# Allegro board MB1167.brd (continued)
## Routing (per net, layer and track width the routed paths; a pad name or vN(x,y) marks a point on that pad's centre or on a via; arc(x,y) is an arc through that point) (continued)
D11: length 133
  TOP w0.102: U9.G4 75.52,103.76 73.51,103.76 72.77,103.02 72.77,102.11 72.11,101.45 72.11,101.09 71.88,100.86 ; 65.9,82.8 65.9,81.42 66.04,81.28 66.04,79.73 U14.D2 ; v5(85.86,82.34) U13.P1
  TOP w0.127: v5(65.28,83.69) 65.34,83.69 65.9,83.14 65.9,82.8 ; CN10.20 v3(54.86,105.97) ; 71.88,100.86 v4(71.65,100.63) ; R55.2 v1(68.58,124.59)
  L4_SIG w0.102: v4(71.65,100.63) 71.6,100.58 69.37,100.58 63.98,105.97 v3(54.86,105.97) ; v5(85.86,82.34) 85.86,82.85 85.58,83.13 74.86,83.13 74.52,82.8 v1(73.66,82.8) 73.46,83.01 66.14,83.01 65.46,83.69 v5(65.28,83.69)
  BOTTOM w0.127: v4(71.65,100.63) 71.09,100.63 70.83,100.37 70.83,100.19 71.7,99.31 71.7,99.13 71.52,98.95 71.34,98.95 70.47,99.83 70.29,99.83 70.11,99.65 70.11,99.47 70.98,98.59 70.98,98.41 70.78,98.21 70.6,98.21 69.72,99.08 69.54,99.08 69.36,98.9 69.36,98.72 70.24,97.85 70.24,97.67 70.06,97.49 69.88,97.49 69.58,97.79 69.4,97.79 69.22,97.61 69.22,97.43 69.52,97.13 69.52,96.95 69.22,96.65 69.22,88.04 69.34,87.91 72.11,87.91 72.24,87.78 72.24,87.53 72.11,87.4 69.34,87.4 69.22,87.27 69.22,87.02 69.34,86.89 73.1,86.89 73.23,86.77 73.23,86.49 73.1,86.36 70.28,86.36 70.15,86.23 70.15,85.98 70.28,85.85 73.43,85.85 73.56,85.72 73.56,85.45 73.43,85.32 71.3,85.32 71.17,85.19 71.17,84.94 71.3,84.81 73.43,84.81 73.56,84.68 73.56,84.43 73.43,84.3 72.31,84.3 72.19,84.18 72.19,83.92 72.31,83.79 73.43,83.79 73.56,83.67 73.56,83.41 73.43,83.29 72.72,83.29 72.59,83.16 72.59,82.93 72.72,82.8 v1(73.66,82.8) ; v1(68.58,124.59) 69.22,123.95 69.22,117.35 57.84,105.97 v3(54.86,105.97)
D12: length 129.8
  TOP w0.102: v5(64.84,81.85) 65.28,81.41 65.28,79.74 U14.E2 ; U9.F5 76.51,102.77 75.67,102.77 75.53,102.63 75.53,101.11 75.19,100.76 73.33,100.76 v4(73.15,100.58) ; v5(86.66,81.54) U13.N2
  TOP w0.127: CN10.17 v3(53.42,107.24) ; R66.2 v1(67.56,121.28)
  L4_SIG w0.102: v3(53.42,107.24) 52.83,106.65 52.83,105.69 53.09,105.44 55.47,105.44 55.57,105.33 55.57,104.42 55.67,104.32 55.9,104.32 56,104.42 56,105.51 56.11,105.61 56.31,105.61 56.41,105.51 56.41,104.42 56.51,104.32 56.72,104.32 56.82,104.42 56.82,105.51 56.92,105.61 57.12,105.61 57.22,105.51 57.22,104.42 57.33,104.32 57.53,104.32 57.63,104.42 57.63,105.51 57.73,105.61 57.94,105.61 58.04,105.51 58.04,104.42 58.14,104.32 58.34,104.32 58.44,104.42 58.44,105.51 58.54,105.61 58.75,105.61 58.85,105.51 58.85,104.42 58.95,104.32 59.15,104.32 59.26,104.42 59.26,105.51 59.36,105.61 59.56,105.61 59.66,105.51 59.66,104.42 59.76,104.32 59.97,104.32 60.07,104.42 60.07,105.51 60.17,105.61 60.37,105.61 60.48,105.51 60.48,104.42 60.58,104.32 60.78,104.32 60.88,104.42 60.88,105.51 60.98,105.61 61.19,105.61 61.29,105.51 61.29,104.42 61.39,104.32 61.59,104.32 61.69,104.42 61.69,105.51 61.8,105.61 62,105.61 62.1,105.51 62.1,104.42 62.2,104.32 62.41,104.32 62.51,104.42 62.51,105.51 62.61,105.61 62.81,105.61 62.91,105.51 62.91,104.42 63.02,104.32 63.22,104.32 63.32,104.42 63.32,105.51 63.42,105.61 63.62,105.61 63.73,105.51 63.73,104.42 63.83,104.32 65.02,104.32 69.14,100.2 72.77,100.2 v4(73.15,100.58) ; v5(86.66,81.54) 86.4,81.54 86.03,81.92 84.84,81.92 84.51,82.25 75.74,82.25 75.59,82.09 v1(74.93,82.09) 74.81,81.98 72.95,81.98 72.85,82.08 72.85,82.3 72.75,82.4 72.55,82.4 72.44,82.3 72.44,82.08 72.34,81.98 64.96,81.98 v5(64.84,81.85)
  BOTTOM w0.127: v4(73.15,100.58) 73.15,98.86 70.36,96.06 70.36,91.16 70.48,91.03 74.8,91.03 74.93,90.91 v1(74.93,82.09) ; v1(67.56,121.28) 67.56,117.6 57.91,107.95 54.13,107.95 v3(53.42,107.24)
D13: length 142.8
  TOP w0.102: 74.15,97.79 75.29,98.93 75.29,100.44 75.91,101.06 U9.G6 ; U13.R1 84.27,81.94 ; 84.27,82.63 84.93,82.63 85.06,82.5 v5(85.06,82.34) ; v5(64.14,81.79) 64.52,81.41 64.52,80.8 64.52,80.79 64.52,79.75 U14.F2
  TOP w0.127: 74.15,97.79 73.41,97.05 73.41,97.03 v4(73.03,96.65) ; 84.27,81.94 84.15,81.94 84.02,82.07 84.02,82.5 84.15,82.63 84.27,82.63 ; CN10.35 53.03,95.81 v3(53.42,96.2) ; R59.2 v1(75.18,124.71)
  L4_SIG w0.102: v5(85.06,82.34) 85.37,82.34 85.5,82.47 85.5,82.7 85.37,82.83 84.76,82.83 84.63,82.7 84.63,82.68 84.51,82.55 84.21,82.55 84.11,82.65 84.11,82.73 84,82.83 83.8,82.83 83.7,82.73 83.7,82.65 83.6,82.55 83.39,82.55 83.29,82.65 83.29,82.73 83.19,82.83 82.99,82.83 82.89,82.73 82.89,82.65 82.79,82.55 82.58,82.55 82.48,82.65 82.48,82.73 82.38,82.83 82.18,82.83 82.07,82.73 82.07,82.65 81.97,82.55 81.77,82.55 81.67,82.65 81.67,82.73 81.57,82.83 81.36,82.83 81.26,82.73 81.26,82.65 81.16,82.55 80.96,82.55 80.85,82.65 80.85,82.73 80.75,82.83 80.55,82.83 80.45,82.73 80.45,82.65 80.35,82.55 80.14,82.55 80.04,82.65 80.04,82.73 79.94,82.83 79.74,82.83 79.64,82.73 79.64,82.65 79.53,82.55 79.33,82.55 79.23,82.65 79.23,82.73 79.13,82.83 78.92,82.83 78.82,82.73 78.82,82.65 78.72,82.55 78.52,82.55 78.42,82.65 78.42,82.73 78.31,82.83 78.11,82.83 78.01,82.73 78.01,82.65 77.91,82.55 77.09,82.55 v1(76.96,82.68) 74.9,82.68 74.56,82.33 73.42,82.33 73.05,82.7 72.24,82.7 71.87,82.33 64.55,82.33 64.14,81.92 v5(64.14,81.79) ; v4(73.03,96.65) 69.9,96.65 69.77,96.52 69.77,95.94 69.65,95.81 66.47,95.81 66.34,95.68 66.34,94.54 66.22,94.41 66.03,94.41 65.91,94.54 65.91,95.66 65.81,95.76 65.6,95.76 65.5,95.66 65.5,94.51 65.4,94.41 65.2,94.41 65.09,94.51 65.09,95.66 64.99,95.76 64.79,95.76 64.69,95.66 64.69,94.51 64.59,94.41 64.38,94.41 64.28,94.51 64.28,95.66 64.18,95.76 63.98,95.76 63.87,95.66 63.87,94.51 63.77,94.41 63.57,94.41 63.47,94.51 63.47,95.66 63.37,95.76 63.16,95.76 63.06,95.66 63.06,94.51 62.96,94.41 62.76,94.41 62.66,94.51 62.66,95.66 62.55,95.76 62.35,95.76 62.25,95.66 62.25,94.51 62.15,94.41 61.94,94.41 61.84,94.51 61.84,95.66 61.74,95.76 61.54,95.76 61.44,95.66 61.44,94.51 61.33,94.41 61.13,94.41 61.03,94.51 61.03,95.66 60.93,95.76 60.73,95.76 60.62,95.66 60.62,94.51 60.52,94.41 60.32,94.41 60.22,94.51 60.22,95.66 60.12,95.76 59.91,95.76 59.81,95.66 59.81,94.51 59.71,94.41 59.51,94.41 59.4,94.51 59.4,95.66 59.3,95.76 59.1,95.76 59,95.66 59,94.51 58.9,94.41 58.69,94.41 58.59,94.51 58.59,95.66 58.49,95.76 58.29,95.76 58.19,95.66 58.19,94.51 58.08,94.41 57.88,94.41 57.78,94.51 57.78,95.66 57.68,95.76 53.85,95.76 v3(53.42,96.2)
  BOTTOM w0.127: v3(53.42,96.2) 53.42,96.2 53.98,96.75 56.62,96.75 74.42,114.55 74.42,121.25 74.8,121.64 74.8,123.44 75.18,123.83 v1(75.18,124.71) ; v4(73.03,96.65) 73.03,96.11 76.96,92.18 v1(76.96,82.68)
D14: length 135.3
  TOP w0.102: U14.F1 v5(64.92,80.64) ; v5(86.66,80.74) U13.N3 ; U9.F6 76.29,100.75 76.29,98.39 75.69,97.79
  TOP w0.127: 75.69,97.79 v4(74.55,96.65) ; CN10.37 53.01,94.54 53.47,95 v3(53.47,95.21) ; v1(75.44,120.75) 75.31,120.75 73.79,122.28 R70.2
  L4_SIG w0.102: v4(74.55,96.65) 74.55,95.1 74.42,94.97 74.12,94.97 73.99,95.1 73.99,96.15 73.86,96.28 73.62,96.28 73.52,96.18 73.52,95 73.41,94.89 73.21,94.89 73.11,95 73.11,96.07 72.99,96.19 72.82,96.19 72.7,96.07 72.7,95 72.6,94.89 72.4,94.89 72.3,95 72.3,96.18 72.2,96.28 71.99,96.28 71.89,96.18 71.89,95 71.79,94.89 71.59,94.89 71.48,95 71.48,96.18 71.38,96.28 70.21,96.28 70.08,96.15 70.08,94.21 69.95,94.08 69.72,94.08 69.62,94.18 69.62,95.4 69.52,95.5 69.31,95.5 69.21,95.4 69.21,94.18 69.11,94.08 68.91,94.08 68.81,94.18 68.81,95.4 68.7,95.5 68.5,95.5 68.4,95.4 68.4,94.18 68.3,94.08 68.09,94.08 67.99,94.18 67.99,95.4 67.89,95.5 67.69,95.5 67.59,95.4 67.59,94.18 67.49,94.08 67.28,94.08 67.18,94.18 67.18,95.4 67.08,95.5 66.88,95.5 66.77,95.4 66.77,94.18 66.67,94.08 57.43,94.08 57.3,94.21 57.3,95.33 57.18,95.45 53.71,95.45 v3(53.47,95.21) ; v5(64.92,80.64) 64.92,80.89 65.39,81.37 71.64,81.37 71.78,81.23 77.27,81.23 v1(77.46,81.42) 77.46,81.06 77.6,80.92 81.03,80.92 81.15,81.05 81.15,81.46 81.28,81.58 81.43,81.58 81.56,81.46 81.56,81.05 81.69,80.92 81.86,80.92 81.99,81.05 81.99,81.46 82.12,81.58 84.18,81.58 84.61,81.15 86.97,81.15 87.1,81.03 87.1,80.87 86.97,80.74 v5(86.66,80.74)
  BOTTOM w0.127: v1(77.46,81.42) 77.85,81.81 77.85,92.43 74.42,95.86 74.42,96.52 v4(74.55,96.65) ; v3(53.47,95.21) 53.89,95.63 56.64,95.63 75.18,114.17 75.18,120.5 v1(75.44,120.75)
D15: length 134.1
  TOP w0.102: U14.G1 v5(64.16,80.64) ; 74.93,97.79 75.53,98.39 75.53,99.99 U9.G7 ; v5(85.06,81.54) U13.R2
  TOP w0.127: 74.93,97.79 v4(73.84,96.7) ; R71.2 75.18,121.67 v1(75.44,121.41) ; v3(54.86,96.24) 54.86,96.19 55.24,95.81 CN10.36
  L4_SIG w0.102: v5(85.06,81.54) 84.73,81.54 84.36,81.91 80.98,81.91 80.85,81.78 80.85,81.38 80.72,81.25 80.59,81.25 80.47,81.38 80.47,81.71 80.34,81.84 80.16,81.84 80.04,81.71 80.04,81.38 79.91,81.25 79.72,81.25 79.62,81.36 79.62,81.82 79.5,81.94 79.34,81.94 79.22,81.82 79.22,81.36 79.12,81.25 78.91,81.25 78.81,81.36 78.81,81.82 78.69,81.94 78.52,81.94 78.4,81.82 78.4,81.36 78.3,81.25 78.1,81.25 78,81.36 78,81.81 77.9,81.91 77.06,81.91 v1(76.96,81.81) 76.81,81.66 65.15,81.66 64.16,80.67 v5(64.16,80.64) ; v4(73.84,96.7) 73.84,96.94 73.71,97.07 69.6,97.07 69.47,96.94 69.47,96.32 69.34,96.19 69.19,96.19 69.06,96.32 69.06,96.88 68.94,97 68.76,97 68.63,96.88 68.63,96.32 68.5,96.19 68.33,96.19 68.22,96.29 68.22,96.98 68.12,97.08 67.92,97.08 67.82,96.98 67.82,96.29 67.72,96.19 67.51,96.19 67.41,96.29 67.41,96.98 67.31,97.08 67.11,97.08 67.01,96.98 67.01,96.29 66.9,96.19 66.7,96.19 66.6,96.29 66.6,96.98 66.5,97.08 66.29,97.08 66.19,96.98 66.19,96.29 66.09,96.19 65.89,96.19 65.79,96.29 65.79,96.98 65.68,97.08 65.48,97.08 65.38,96.98 65.38,96.29 65.28,96.19 65.08,96.19 64.97,96.29 64.97,96.98 64.87,97.08 64.67,97.08 64.57,96.98 64.57,96.29 64.47,96.19 64.26,96.19 64.16,96.29 64.16,96.98 64.06,97.08 63.86,97.08 63.75,96.98 63.75,96.18 63.64,96.06 63.47,96.06 63.35,96.18 63.35,96.98 63.25,97.08 63.04,97.08 62.94,96.98 62.94,96.18 62.82,96.06 62.65,96.06 62.54,96.18 62.54,96.98 62.43,97.08 62.23,97.08 62.13,96.98 62.13,96.18 62.01,96.06 61.84,96.06 61.72,96.18 61.72,96.98 61.62,97.08 61.42,97.08 61.32,96.98 61.32,96.18 61.2,96.06 61.03,96.06 60.91,96.18 60.91,96.98 60.81,97.08 60.6,97.08 60.5,96.98 60.5,96.21 60.38,96.09 60.22,96.09 60.1,96.21 60.1,96.98 60,97.08 59.79,97.08 59.69,96.98 59.69,96.23 59.57,96.11 59.4,96.11 59.28,96.23 59.28,96.98 59.18,97.08 58.98,97.08 58.88,96.98 58.88,96.18 58.76,96.06 58.59,96.06 58.47,96.18 58.47,96.98 58.37,97.08 58.17,97.08 58.06,96.98 58.06,96.21 57.95,96.09 57.78,96.09 57.66,96.21 57.66,96.98 57.56,97.08 57.35,97.08 57.25,96.98 57.25,96.18 57.13,96.06 56.96,96.06 56.85,96.18 56.85,96.98 56.74,97.08 56.54,97.08 56.44,96.98 56.44,96.18 56.32,96.06 56.15,96.06 56.03,96.18 56.03,96.83 55.91,96.95 55.75,96.95 55.63,96.83 55.63,96.29 55.52,96.19 54.91,96.19 v3(54.86,96.24)
  BOTTOM w0.127: v3(54.86,96.24) 55.09,96.01 56.48,96.01 74.8,114.33 74.8,120.9 75.31,121.41 v1(75.44,121.41) ; v4(73.84,96.7) 73.79,96.65 73.79,95.9 77.47,92.22 77.47,82.19 77.09,81.81 v1(76.96,81.81)
D16: length 117.6
  TOP w0.102: U13.E8 93.85,75.95 93.85,74.66
  TOP w0.127: 93.85,74.66 93.85,74.3 v5(95.25,72.9) ; v1(70.87,124.71) 70.99,124.84 R56.1 ; CN10.22 v3(54.86,104.7)
  L4_SIG w0.102: v3(54.86,104.7) 54.46,104.7 54.03,105.13 52.63,105.13 51.66,104.17 51.66,91.37 51.77,91.27 52.08,91.27 52.2,91.15 52.2,90.98 52.08,90.86 51.77,90.86 51.66,90.76 51.66,90.55 51.77,90.45 52.92,90.45 53.04,90.33 53.04,90.17 52.92,90.05 51.77,90.05 51.66,89.94 51.66,89.74 51.77,89.64 53.73,89.64 53.85,89.52 53.85,89.35 53.73,89.23 51.77,89.23 51.66,89.13 51.66,84.45 66.62,69.49 88.9,69.49 92.3,72.9 v5(95.25,72.9)
  BOTTOM w0.127: v3(54.86,104.7) 57.93,104.7 69.98,116.74 69.98,123.83 v1(70.87,124.71)
D17: length 120.5
  TOP w0.102: v5(94.66,76.74) U13.D7
  TOP w0.127: CN10.26 v3(54.86,102.16) ; R57.1 v1(72.39,124.71)
  L4_SIG w0.102: v3(54.86,102.16) 54.18,102.16 53.59,102.74 52.96,102.74 52.27,102.06 52.27,92.08 54.46,89.89 54.46,86.97 54.36,86.87 52.43,86.87 52.32,86.77 52.32,86.56 52.43,86.46 54.16,86.46 54.28,86.34 54.28,86.17 54.16,86.06 52.43,86.06 52.32,85.95 52.32,85.75 52.43,85.65 54.08,85.65 54.2,85.53 54.2,85.36 54.08,85.24 52.43,85.24 52.32,85.14 52.32,84.76 66.95,70.13 88.6,70.13 92.51,74.04 95.76,74.04 96.27,74.55 96.27,75.31 95.89,75.69 95.89,76.23 95.78,76.33 95.07,76.33 v5(94.66,76.74)
  BOTTOM w0.127: v3(54.86,102.16) 57.71,102.16 71.5,115.95 71.5,120.27 71.88,120.65 71.88,123.95 72.39,124.46 v1(72.39,124.71)
D18: length 116.6
  TOP w0.102: 94.7,74.66 94.7,75.9 U13.D8
  TOP w0.127: R68.1 v1(70.99,121.28) ; v5(95.22,73.53) 95.22,73.81 94.7,74.33 94.7,74.66 ; CN10.24 v3(54.86,103.43)
  L4_SIG w0.102: v5(95.22,73.53) 92.46,73.53 88.72,69.8 66.83,69.8 51.97,84.66 51.97,87.19 52.07,87.29 54.05,87.29 54.15,87.39 54.15,87.59 54.05,87.7 52.07,87.7 51.97,87.8 51.97,88 52.07,88.1 54.05,88.1 54.15,88.2 54.15,88.41 54.05,88.51 52.07,88.51 51.97,88.61 51.97,88.81 52.07,88.91 54.05,88.91 54.15,89.02 54.15,89.69 51.97,91.87 51.97,103.15 52.83,104.01 53.59,104.01 54.18,103.43 v3(54.86,103.43)
  BOTTOM w0.127: v1(70.99,121.28) 70.74,121.03 70.74,116.36 57.81,103.43 v3(54.86,103.43)
D19: length 115.2
  TOP w0.102: v5(95.86,74.68) U13.B9
  TOP w0.127: v1(72,119.9) 72,120 72.39,120.4 R69.1 ; CN10.27 v3(53.42,100.89)
  L4_SIG w0.102: v3(53.42,100.89) 52.58,100.05 52.58,92.3 54.79,90.09 54.79,89.81 54.89,89.7 55.19,89.7 55.32,89.58 55.32,89.43 55.19,89.3 54.89,89.3 54.79,89.2 54.79,88.99 54.89,88.89 55.8,88.89 55.91,88.79 55.91,88.59 55.8,88.49 54.89,88.49 54.79,88.38 54.79,88.18 54.89,88.08 55.8,88.08 55.91,87.98 55.91,87.77 55.8,87.67 54.89,87.67 54.79,87.57 54.79,87.37 54.89,87.27 55.8,87.27 55.91,87.16 55.91,86.96 55.8,86.86 54.89,86.86 54.79,86.76 54.79,86.56 54.89,86.45 55.8,86.45 55.91,86.35 55.91,86.15 55.8,86.05 54.89,86.05 54.79,85.95 54.79,84.91 54.69,84.81 53.13,84.81 53.01,84.69 53.01,84.52 53.13,84.4 54.69,84.4 54.79,84.3 54.79,84.1 54.69,84 54,84 53.9,83.89 53.9,83.69 54,83.59 54.69,83.59 54.79,83.49 54.79,82.73 67.08,70.43 88.47,70.43 92.46,74.42 95.61,74.42 v5(95.86,74.68)
  BOTTOM w0.127: v1(72,119.9) 72,115.86 57.73,101.6 54.13,101.6 v3(53.42,100.89)
D20: length 118.4
  TOP w0.102: v5(95.46,75.94) U13.C8
  TOP w0.127: R58.1 v1(73.79,124.71) ; CN10.32 v3(54.86,98.35)
  L4_SIG w0.102: v3(54.86,98.35) 54.15,99.06 53.42,99.06 52.88,98.53 52.88,92.46 56.21,89.13 56.21,85.8 56.11,85.7 55.19,85.7 55.09,85.6 55.09,85.39 55.19,85.29 56.11,85.29 56.21,85.19 56.21,84.99 56.11,84.89 55.19,84.89 55.09,84.78 55.09,84.58 55.19,84.48 56.11,84.48 56.21,84.38 56.21,84.17 56.11,84.07 55.19,84.07 55.09,83.97 55.09,83.77 55.19,83.67 56.11,83.67 56.21,83.56 56.21,83.36 56.11,83.26 55.19,83.26 55.09,83.16 55.09,82.96 55.19,82.85 56.11,82.85 56.21,82.75 56.21,81.81 67.21,70.82 88.37,70.82 92.25,74.7 92.25,76.05 92.38,76.17 92.66,76.17 92.79,76.05 92.79,75.39 92.91,75.26 93.17,75.26 93.29,75.39 93.29,76.05 93.42,76.17 93.63,76.17 93.76,76.05 93.76,75.34 93.86,75.23 94.06,75.23 94.16,75.34 94.16,76.08 94.28,76.2 94.45,76.2 94.57,76.08 94.57,75.34 94.67,75.23 94.88,75.23 94.98,75.34 94.98,75.84 95.08,75.94 v5(95.46,75.94)
  BOTTOM w0.127: v1(73.79,124.71) 73.79,124.15 73.27,123.63 73.27,115.44 56.18,98.35 v3(54.86,98.35)
D21: length 115.3
  TOP w0.102: v5(97.06,75.14) U13.A9
  TOP w0.127: v3(101.85,92.46) 101.04,93.27 CN11.39
  L4_SIG w0.102: v5(97.06,75.14) 96.65,75.55 96.65,76.94 97.66,77.95 97.66,87.68 101.85,91.87 v3(101.85,92.46)
  BOTTOM w0.127: v3(101.85,92.46) 87.6,92.46 87.35,92.71 87.35,104.02 87.22,104.14 86,104.14 85.83,104.32 85.83,104.61 85.95,104.74 87.22,104.74 87.35,104.87 87.35,105.12 87.22,105.25 85.95,105.25 85.83,105.38 85.83,107.49 85.7,107.62 85.19,107.62 85.06,107.75 85.06,108 85.19,108.13 85.7,108.13 85.83,108.25 85.83,108.64 85.34,109.12 84.83,109.12 84.67,108.96 84.49,108.96 84.31,109.14 84.31,109.32 84.58,109.6 84.58,109.78 84.41,109.96 84.23,109.96 83.95,109.68 83.77,109.68 83.59,109.86 83.59,110.04 83.75,110.2 83.75,110.38 83.52,110.62 83.2,110.62 83.08,110.74 83.08,111.15 82.95,111.28 82.69,111.28 82.57,111.15 82.57,110.31 82.44,110.19 82.06,110.19 81.93,110.31 81.93,111.25 81.81,111.38 81.55,111.38 81.43,111.25 81.43,110.74 81.3,110.62 81.05,110.62 80.92,110.74 80.92,111.25 80.79,111.38 79.86,111.38 79.73,111.25 79.73,110.74 79.6,110.62 79.35,110.62 79.22,110.74 79.22,111.25 79.1,111.38 78.74,111.38 78.61,111.25 78.61,110.82 78.49,110.69 78.18,110.69 78.05,110.82 78.05,115.64 78.18,115.76 79.98,115.76 80.11,115.89 80.11,116.14 79.98,116.27 78.18,116.27 78.05,116.4 78.05,116.65 78.18,116.78 79.98,116.78 80.11,116.91 80.11,117.16 79.98,117.29 78.18,117.29 78.05,117.41 78.05,117.67 78.18,117.8 79.98,117.8 80.11,117.92 80.11,118.18 79.98,118.3 78.18,118.3 78.05,118.43 78.05,118.68 78.18,118.81 79.98,118.81 80.11,118.94 80.11,119.19 79.98,119.32 78.18,119.32 78.05,119.45 78.05,119.7 78.18,119.83 79.98,119.83 80.11,119.95 80.11,120.21 79.98,120.34 78.18,120.34 78.05,120.46 78.05,120.72 78.18,120.84 79.98,120.84 80.11,120.97 80.11,121.14 79.98,121.27 79.5,121.27 79.38,121.39 79.38,121.65 79.5,121.78 79.98,121.78 80.11,121.9 80.11,122.16 79.98,122.28 79.63,122.28 79.5,122.41 79.5,122.66 79.63,122.79 79.98,122.79 80.11,122.92 80.11,123.21 79.98,123.34 79.63,123.34 79.5,123.46 79.5,123.72 79.63,123.84 80.62,123.84 80.75,123.97 80.75,124.31 80.62,124.43 79.63,124.43 79.5,124.56 79.5,125.09 79.63,125.22 R271.1
D22: length 113
  TOP w0.102: v5(95.46,76.74) U13.C7
  TOP w0.127: CN11.38 103.96,94.54 v3(103.5,95)
  L4_SIG w0.102: v5(95.46,76.74) 96.7,77.98 96.7,78.65 96.8,78.75 97.1,78.75 97.21,78.85 97.21,79.06 97.1,79.16 96.8,79.16 96.7,79.26 96.7,79.46 96.8,79.57 97.1,79.57 97.21,79.67 97.21,79.87 97.1,79.97 96.8,79.97 96.7,80.07 96.7,90.48 101.73,95.5 103,95.5 v3(103.5,95)
  BOTTOM w0.127: v3(103.5,95) 103.89,94.61 103.89,93.47 103.25,92.84 102.23,92.84 101.98,93.09 87.88,93.09 87.76,93.22 87.76,93.45 87.88,93.57 89.36,93.57 89.48,93.7 89.48,94.04 89.36,94.17 87.88,94.17 87.76,94.29 87.76,94.55 87.88,94.67 89.36,94.67 89.48,94.8 89.48,95.05 89.36,95.18 87.88,95.18 87.76,95.31 87.76,95.56 87.88,95.69 89.36,95.69 89.48,95.82 89.48,96.07 89.36,96.2 87.88,96.2 87.76,96.32 87.76,96.58 87.88,96.71 89.36,96.71 89.48,96.83 89.48,101.52 89.36,101.65 87.91,101.65 87.78,101.78 87.78,105.28 87.39,105.67 86.39,105.67 86.26,105.8 86.26,108.81 83.29,111.79 78.56,111.79 78.44,111.91 78.44,112.17 78.56,112.29 82.3,112.29 82.42,112.42 82.42,112.65 82.3,112.78 78.56,112.78 78.44,112.9 78.44,113.2 78.56,113.33 80.75,113.33 80.87,113.45 80.87,113.71 80.75,113.84 78.56,113.84 78.44,113.96 78.44,114.22 78.56,114.34 80.72,114.34 80.85,114.47 80.85,114.72 80.72,114.85 78.56,114.85 78.44,114.98 78.44,115.23 78.56,115.36 80.52,115.36 80.64,115.49 R279.1
D23: length 113.3
  TOP w0.102: v5(97.06,75.94) U13.A8
  TOP w0.127: CN11.36 103.71,95.81 v3(103.5,96.01)
  L4_SIG w0.102: v3(103.5,96.01) 103.76,96.01 104.17,95.61 104.17,93.6 98.04,87.48 98.04,76.93 v5(97.06,75.94)
  BOTTOM w0.127: R278.1 82.42,121.79 82.52,121.69 82.52,121.34 82.4,121.21 81.81,121.21 81.69,121.08 81.69,120.83 81.81,120.7 82.4,120.7 82.52,120.57 82.52,120.32 82.4,120.19 81.81,120.19 81.69,120.07 81.69,119.81 81.81,119.68 82.4,119.68 82.52,119.56 82.52,119.3 82.4,119.18 81.81,119.18 81.69,119.05 81.69,118.8 81.81,118.67 82.4,118.67 82.52,118.54 82.52,118.29 82.4,118.16 81.81,118.16 81.69,118.03 81.69,117.78 81.81,117.65 82.4,117.65 82.52,117.53 82.52,117.27 82.4,117.14 81.81,117.14 81.69,117.02 81.69,116.76 81.81,116.64 82.4,116.64 82.52,116.51 82.52,116.26 82.4,116.13 81.81,116.13 81.69,116 81.69,115.75 81.81,115.62 82.4,115.62 82.52,115.49 82.52,114.66 83.15,114.03 83.15,113.85 82.85,113.54 82.85,113.36 83.03,113.18 83.21,113.18 83.51,113.49 83.69,113.49 83.87,113.31 83.87,113.13 83.57,112.83 83.57,112.65 83.75,112.47 83.93,112.47 84.23,112.77 84.41,112.77 84.59,112.59 84.59,112.41 84.29,112.11 84.29,111.93 84.47,111.75 84.65,111.75 84.95,112.05 85.13,112.05 85.31,111.87 85.31,111.69 85.01,111.39 85.01,111.21 85.19,111.03 85.37,111.03 85.67,111.33 85.85,111.33 86.03,111.15 86.03,110.97 85.73,110.67 85.73,110.49 85.91,110.31 86.09,110.31 86.39,110.61 86.57,110.61 86.75,110.43 86.75,110.25 86.45,109.95 86.45,109.77 86.62,109.59 86.8,109.59 87.11,109.89 87.29,109.89 87.47,109.71 87.47,109.53 87.16,109.23 87.16,109.05 87.34,108.87 87.52,108.87 87.83,109.17 88.01,109.17 88.19,108.99 88.19,108.81 87.88,108.51 87.88,108.33 88.06,108.15 88.24,108.15 88.54,108.46 88.72,108.46 88.9,108.28 88.9,108.1 88.6,107.79 88.6,107.61 88.78,107.43 88.96,107.43 89.26,107.74 89.44,107.74 89.62,107.56 89.62,107.38 89.32,107.07 89.32,106.89 89.5,106.72 89.68,106.72 89.98,107.02 90.16,107.02 90.34,106.84 90.34,106.66 90.04,106.36 90.04,106.18 90.22,106 90.4,106 90.7,106.3 90.88,106.3 91.06,106.12 91.06,105.94 90.71,105.59 90.09,105.59 89.97,105.46 89.97,105.21 90.09,105.08 90.63,105.08 90.76,104.95 90.76,104.67 90.63,104.55 90.09,104.55 89.97,104.42 89.97,104.14 90.09,104.01 90.86,104.01 90.98,103.89 90.98,103.2 90.86,103.07 90.4,103.07 90.27,102.94 90.27,102.69 90.4,102.56 90.86,102.56 90.98,102.44 90.98,95.63 91.11,95.5 92.06,95.5 92.19,95.38 92.19,94.03 92.32,93.9 92.57,93.9 92.7,94.03 92.7,95.38 92.83,95.5 93.08,95.5 93.21,95.38 93.21,94.03 93.33,93.9 93.59,93.9 93.71,94.03 93.71,95.38 93.84,95.5 94.1,95.5 94.22,95.38 94.22,94.03 94.35,93.9 94.6,93.9 94.73,94.03 94.73,95.38 94.86,95.5 95.11,95.5 95.24,95.38 95.24,94.03 95.37,93.9 95.62,93.9 95.75,94.03 95.75,95.38 95.87,95.5 96.13,95.5 96.25,95.38 96.25,94.03 96.38,93.9 96.64,93.9 96.76,94.03 96.76,95.38 96.89,95.5 97.14,95.5 97.27,95.38 97.27,94.03 97.4,93.9 97.65,93.9 97.78,94.03 97.78,95.38 97.91,95.5 98.16,95.5 98.29,95.38 98.29,94.03 98.41,93.9 100.97,93.9 101.09,94.03 101.09,95.38 101.22,95.5 102.87,95.5 103.38,96.01 v3(103.5,96.01)
D24: length 118.1
  TOP w0.127: v5(97.28,81.68) 97.2,81.68 U13.A2 ; v3(101.98,95.01) 101.85,94.88 101.85,94.87 101.52,94.54 CN11.37
  L4_SIG w0.102: v3(101.98,95.01) 101.94,95.01 100.91,93.97 100.91,93.83 101.6,93.13 101.6,92.96 101.48,92.85 101.31,92.85 100.62,93.54 100.47,93.54 100.33,93.4 100.33,93.25 101.47,92.11 101.47,91.97 101.33,91.83 101.18,91.83 100.04,92.96 99.9,92.96 99.76,92.82 99.76,92.68 100.89,91.54 100.89,91.39 100.75,91.25 100.61,91.25 99.47,92.39 99.32,92.39 99.18,92.25 99.18,92.1 100.32,90.96 100.32,90.82 100.18,90.68 100.03,90.68 98.89,91.81 98.75,91.81 98.61,91.67 98.61,91.53 99.74,90.39 99.74,90.24 99.6,90.1 99.46,90.1 98.32,91.24 98.17,91.24 98.03,91.1 98.03,90.95 99.17,89.81 99.17,89.67 99.02,89.52 98.87,89.52 97.71,90.68 97.56,90.68 97.42,90.54 97.42,90.39 98.59,89.23 98.59,89.09 98.44,88.94 98.3,88.94 97.35,89.89 97.18,89.89 97.06,89.77 97.06,89.6 98.01,88.65 98.01,88.51 97.83,88.34 97.69,88.34 97.43,88.6 97.28,88.6 97.14,88.45 97.14,88.31 97.4,88.05 97.4,87.9 97.28,87.78 v5(97.28,81.68)
  BOTTOM w0.127: R270.1 82.17,125.09 82.17,123.95 81.28,123.06 81.28,114.38 86.66,108.99 86.66,108.31 86.79,108.18 87.43,108.18 87.55,108.05 87.55,107.8 87.43,107.67 86.79,107.67 86.66,107.54 86.66,107.29 86.79,107.16 88.49,107.16 88.62,107.04 88.62,106.78 88.49,106.65 86.79,106.65 86.66,106.53 86.66,106.22 86.79,106.1 89.41,106.1 89.53,105.97 89.53,105.66 89.41,105.54 88.32,105.54 88.19,105.41 88.19,105.16 88.32,105.03 89.41,105.03 89.53,104.9 89.53,104.65 89.41,104.52 88.32,104.52 88.19,104.39 88.19,104.14 88.32,104.01 89.41,104.01 89.53,103.89 89.53,103.63 89.41,103.51 88.32,103.51 88.19,103.38 88.19,103.12 88.32,103 89.41,103 89.53,102.87 89.53,102.62 89.41,102.49 88.32,102.49 88.19,102.36 88.19,102.16 88.32,102.03 90.42,102.03 90.55,101.9 90.55,100.92 90.42,100.79 90.02,100.79 89.89,100.67 89.89,100.41 90.02,100.29 90.45,100.29 90.58,100.16 90.58,99.9 90.45,99.78 90.02,99.78 89.89,99.65 89.89,99.4 90.02,99.27 90.45,99.27 90.58,99.14 90.58,98.89 90.45,98.76 90.02,98.76 89.89,98.63 89.89,98.38 90.02,98.25 90.45,98.25 90.58,98.13 90.58,97.87 90.45,97.75 90.02,97.75 89.89,97.62 89.89,97.36 90.02,97.24 90.45,97.24 90.58,97.11 90.58,96.86 90.45,96.73 90.02,96.73 89.89,96.6 89.89,96.35 90.02,96.22 90.45,96.22 90.58,96.09 90.58,95.84 90.45,95.71 90.02,95.71 89.89,95.59 89.89,95.33 90.02,95.21 90.45,95.21 90.58,95.08 90.58,94.82 90.45,94.7 90.02,94.7 89.89,94.57 89.89,94.32 90.02,94.19 90.45,94.19 90.58,94.06 90.58,93.62 90.7,93.5 90.97,93.5 91.1,93.62 91.1,95 91.23,95.12 91.48,95.12 91.61,95 91.61,93.62 91.74,93.5 101.22,93.5 101.47,93.75 101.47,94.92 101.55,95 101.97,95 v3(101.98,95.01)
D25: length 117.4
  TOP w0.102: v5(95.46,80.74) U13.C3
  TOP w0.127: CN11.35 101.78,95.81 v3(101.98,96.01)
  L4_SIG w0.102: v3(101.98,96.01) 101.7,96.01 96.29,90.6 96.29,82.08 95.9,81.69 95.9,78.97 95.78,78.84 95.59,78.84 95.46,78.97 v5(95.46,80.74)
  BOTTOM w0.127: R269.1 82.93,124.71 82.93,114.83 91.47,106.3 91.47,96.14 91.59,96.01 91.93,96.01 92.06,96.14 92.06,98.76 92.19,98.88 92.44,98.88 92.57,98.76 92.57,96.14 92.7,96.01 92.95,96.01 93.08,96.14 93.08,98.76 93.2,98.88 93.46,98.88 93.59,98.76 93.59,96.14 93.71,96.01 93.97,96.01 94.09,96.14 94.09,98.76 94.22,98.88 94.47,98.88 94.6,98.76 94.6,96.14 94.73,96.01 94.98,96.01 95.11,96.14 95.11,98.76 95.24,98.88 95.49,98.88 95.62,98.76 95.62,96.14 95.74,96.01 96,96.01 96.13,96.14 96.13,98.76 96.25,98.88 96.51,98.88 96.63,98.76 96.63,96.14 96.76,96.01 97.01,96.01 97.14,96.14 97.14,98.76 97.27,98.88 97.52,98.88 97.65,98.76 97.65,96.14 97.78,96.01 98.09,96.01 98.22,96.14 98.22,98.73 98.35,98.86 98.63,98.86 98.76,98.73 98.76,94.44 98.88,94.31 99.42,94.31 99.54,94.44 99.54,97.71 99.67,97.84 99.92,97.84 100.05,97.71 100.05,94.44 100.18,94.31 100.53,94.31 100.66,94.44 100.66,96.6 100.79,96.72 101.04,96.72 101.17,96.6 101.17,96.14 101.3,96.01 v3(101.98,96.01)
D26: length 117.1
  TOP w0.127: CN11.33 v3(102.03,97.08) ; U13.A1 96.67,81.94 96.9,82.17 98.17,82.17 v1(98.55,81.79)
  L4_SIG w0.102: v1(98.55,81.79) 98.55,86.46 104.6,92.51 104.6,98.78 104.47,98.91 104.22,98.91 104.09,98.78 104.09,97.87 103.96,97.74 103.07,97.74 102.95,97.61 102.95,97.21 102.82,97.08 v3(102.03,97.08)
  BOTTOM w0.127: v3(102.03,97.08) 101.8,97.08 96.6,102.29 95.59,102.29 95.46,102.41 95.46,103.58 95.33,103.71 95.08,103.71 94.95,103.58 94.95,102.41 94.83,102.29 94.57,102.29 94.45,102.41 94.45,104.6 94.32,104.72 94.06,104.72 93.94,104.6 93.94,102.41 93.81,102.29 93.56,102.29 93.43,102.41 93.43,105.74 93.3,105.87 93.05,105.87 92.92,105.74 92.92,102.39 92.79,102.26 92.35,102.26 92.23,102.39 92.23,106.65 86.82,112.06 86.82,112.84 86.69,112.97 85.9,112.97 85.78,113.1 85.78,113.35 85.9,113.48 86.69,113.48 86.82,113.61 86.82,113.86 86.69,113.99 86.13,113.99 86,114.11 86,114.37 86.13,114.5 86.69,114.5 86.82,114.62 86.82,114.88 86.69,115 84.07,115 83.95,115.13 83.95,115.38 84.07,115.51 86.69,115.51 86.82,115.64 86.82,115.89 86.69,116.02 84.1,116.02 83.97,116.15 83.97,116.4 84.1,116.53 86.69,116.53 86.82,116.65 86.82,116.91 86.69,117.04 84.1,117.04 83.97,117.16 83.97,117.42 84.1,117.54 86.69,117.54 86.82,117.67 86.82,117.92 86.69,118.05 84.07,118.05 83.95,118.18 83.95,118.43 84.07,118.56 86.69,118.56 86.82,118.69 86.82,118.94 86.69,119.07 84.07,119.07 83.95,119.19 83.95,119.45 84.07,119.58 86.69,119.58 86.82,119.7 86.82,119.96 86.69,120.08 84.07,120.08 83.95,120.21 83.95,120.46 84.07,120.59 86.69,120.59 86.82,120.72 86.82,120.93 86.69,121.06 84.45,121.06 84.33,121.18 84.33,124.08 84.84,124.59 R268.1
D27: length 112.7
  TOP w0.102: v5(95.46,81.54) U13.C2
  TOP w0.127: CN11.34 v3(103.5,97.08)
  L4_SIG w0.102: v5(95.46,81.54) 95.46,81.77 95.94,82.25 95.94,85.71 95.83,85.81 94.86,85.81 94.74,85.93 94.74,86.1 94.86,86.22 95.83,86.22 95.94,86.32 95.94,86.52 95.83,86.62 94.77,86.62 94.67,86.72 94.67,86.93 94.77,87.03 95.83,87.03 95.94,87.13 95.94,87.33 95.83,87.43 94.77,87.43 94.67,87.54 94.67,87.74 94.77,87.84 95.83,87.84 95.94,87.94 95.94,88.15 95.83,88.25 94.77,88.25 94.67,88.35 94.67,88.55 94.77,88.65 95.83,88.65 95.94,88.76 95.94,88.96 95.83,89.06 94.77,89.06 94.67,89.16 94.67,89.37 94.77,89.47 95.83,89.47 95.94,89.57 95.94,89.77 95.83,89.87 94.77,89.87 94.67,89.97 94.67,90.18 94.77,90.28 95.82,90.28 95.94,90.4 95.94,90.75 96.08,90.9 96.08,91.04 95.64,91.48 95.64,91.63 95.78,91.77 95.93,91.77 96.37,91.33 96.51,91.33 96.65,91.47 96.65,91.62 96.21,92.06 96.21,92.2 96.36,92.35 96.5,92.35 96.94,91.9 97.09,91.9 97.23,92.05 97.23,92.19 96.79,92.63 96.79,92.78 96.93,92.92 97.08,92.92 97.52,92.48 97.66,92.48 97.8,92.62 97.8,92.77 97.36,93.21 97.36,93.35 97.51,93.5 97.65,93.5 98.09,93.05 98.24,93.05 98.38,93.2 98.38,93.34 97.94,93.78 97.94,93.93 98.08,94.07 98.23,94.07 98.67,93.63 98.81,93.63 98.96,93.77 98.96,93.92 98.51,94.36 98.51,94.5 98.66,94.65 98.8,94.65 99.24,94.2 99.39,94.2 99.53,94.35 99.53,94.49 99.09,94.93 99.09,95.08 99.23,95.22 99.38,95.22 99.82,94.78 99.96,94.78 100.11,94.92 100.11,95.07 99.66,95.51 99.66,95.65 99.81,95.8 99.95,95.8 100.39,95.35 100.54,95.35 100.68,95.5 100.68,95.64 100.24,96.08 100.24,96.23 100.38,96.37 100.53,96.37 100.97,95.93 101.11,95.93 101.26,96.07 101.26,96.22 100.81,96.66 100.81,96.8 100.96,96.95 101.1,96.95 101.53,96.52 103.28,96.52 103.5,96.75 v3(103.5,97.08)
  BOTTOM w0.127: v3(103.5,97.08) 103.05,97.08 102.49,96.52 101.8,96.52 98.98,99.34 98.08,99.34 97.95,99.47 97.95,100.3 97.82,100.43 97.57,100.43 97.44,100.3 97.44,99.47 97.32,99.34 97.06,99.34 96.94,99.47 96.94,101.17 96.81,101.3 96.55,101.3 96.43,101.17 96.43,99.47 96.3,99.34 96.05,99.34 95.92,99.47 95.92,101.63 95.79,101.75 95.54,101.75 95.41,101.63 95.41,99.47 95.28,99.34 95.03,99.34 94.9,99.47 94.9,101.63 94.78,101.75 94.52,101.75 94.4,101.63 94.4,99.47 94.27,99.34 94.01,99.34 93.89,99.47 93.89,101.63 93.76,101.75 93.51,101.75 93.38,101.63 93.38,99.47 93.25,99.34 93,99.34 92.87,99.47 92.87,101.63 92.74,101.75 92.49,101.75 92.36,101.63 92.36,99.47 92.24,99.34 91.97,99.34 91.85,99.47 91.85,106.48 83.36,114.96 83.36,121.01 83.57,121.21 R277.1
D28: length 116.3
  TOP w0.127: U13.B1 96.6,82.68 98.6,82.68 99.42,81.86 v5(99.42,81.84) ; CN11.22 v3(103.38,104.7)
  L4_SIG w0.102: v5(99.42,81.84) 99.42,86.41 99.54,86.54 100.32,86.54 100.45,86.66 100.45,87.4 100.55,87.5 100.75,87.5 100.85,87.4 100.85,86.64 100.95,86.54 101.16,86.54 101.26,86.64 101.26,88.25 101.38,88.37 101.55,88.37 101.67,88.25 101.67,86.64 101.77,86.54 101.97,86.54 102.07,86.64 102.07,89.06 102.19,89.18 102.36,89.18 102.48,89.06 102.48,86.64 102.58,86.54 102.78,86.54 102.88,86.64 102.88,89.85 103,89.97 103.17,89.97 103.29,89.85 103.29,86.64 103.39,86.54 103.6,86.54 103.7,86.64 103.7,90.69 103.82,90.81 103.98,90.81 104.1,90.69 104.1,86.64 104.21,86.54 104.41,86.54 104.51,86.64 104.51,91.5 104.63,91.62 104.8,91.62 104.92,91.5 104.92,86.64 105.02,86.54 105.23,86.54 105.36,86.66 105.36,100.53 105.23,100.66 103.99,100.66 103.86,100.79 103.86,101.09 103.96,101.2 105.31,101.2 105.41,101.3 105.41,101.5 105.31,101.6 103.96,101.6 103.86,101.7 103.86,101.91 103.96,102.01 105.32,102.01 105.44,102.13 105.44,102.3 105.32,102.41 103.96,102.41 103.86,102.52 103.86,104.57 103.73,104.7 v3(103.38,104.7)
  BOTTOM w0.127: R250.1 90.3,135.51 90.3,115.16 101.37,104.09 102.44,104.09 103.05,104.7 v3(103.38,104.7)
D29: length 115
  TOP w0.102: U13.D2 94.61,80.78 94.61,80.14 95.12,79.63 97.73,79.63
  TOP w0.127: CN11.18 v3(103.38,107.24) ; v1(98.81,80.64) 97.79,79.63 97.73,79.63
  L4_SIG w0.102: v1(98.81,80.64) 98.81,75.18 98.93,75.06 99.14,75.06 99.26,75.18 99.26,79.65 99.44,79.83 100.84,79.83 100.97,79.96 100.97,81.48 101.09,81.61 101.24,81.61 101.34,81.51 101.34,79.93 101.44,79.83 101.64,79.83 101.75,79.93 101.75,81.51 101.85,81.61 102.05,81.61 102.15,81.51 102.15,79.93 102.25,79.83 102.46,79.83 102.56,79.93 102.56,81.51 102.66,81.61 102.86,81.61 102.96,81.51 102.96,79.93 103.07,79.83 103.27,79.83 103.37,79.93 103.37,81.51 103.47,81.61 103.68,81.61 103.78,81.51 103.78,79.93 103.88,79.83 104.08,79.83 104.18,79.93 104.18,81.51 104.29,81.61 104.49,81.61 104.59,81.51 104.59,79.93 104.69,79.83 104.9,79.83 105,79.93 105,81.51 105.1,81.61 105.3,81.61 105.4,81.51 105.4,79.93 105.5,79.83 105.71,79.83 105.81,79.93 105.81,81.51 105.91,81.61 106.27,81.61 106.4,81.74 106.4,105.66 104.83,107.24 v3(103.38,107.24)
  BOTTOM w0.127: v3(103.38,107.24) 102.79,106.65 101.55,106.65 91.82,116.38 91.82,133.98 92.46,134.61 92.46,136.65 91.66,137.45 91.66,138.85 R245.1
D30: length 114.2
  TOP w0.102: U13.D3 94.26,79.86 94.87,79.25 97.73,79.25
  TOP w0.127: v1(99.57,80.64) 98.17,79.25 97.73,79.25 ; CN11.20 v3(103.38,105.97)
  L4_SIG w0.102: v1(99.57,80.64) 100.08,80.14 100.53,80.14 100.66,80.26 100.66,81.17 100.53,81.3 100.23,81.3 100.13,81.4 100.13,84.05 100.25,84.18 100.59,84.18 100.69,84.07 100.69,82.02 100.79,81.92 101,81.92 101.1,82.02 101.1,84.07 101.2,84.18 101.4,84.18 101.5,84.07 101.5,82.02 101.61,81.92 101.81,81.92 101.91,82.02 101.91,84.07 102.01,84.18 102.22,84.18 102.32,84.07 102.32,82.02 102.42,81.92 102.62,81.92 102.72,82.02 102.72,84.07 102.83,84.18 103.03,84.18 103.13,84.07 103.13,82.02 103.23,81.92 103.43,81.92 103.54,82.02 103.54,84.07 103.64,84.18 103.84,84.18 103.94,84.07 103.94,82.02 104.04,81.92 104.25,81.92 104.35,82.02 104.35,84.07 104.45,84.18 104.65,84.18 104.76,84.07 104.76,82.02 104.86,81.92 105.06,81.92 105.16,82.02 105.16,84.07 105.26,84.18 105.49,84.18 105.61,84.05 105.61,82.14 105.74,82.02 105.94,82.02 106.07,82.14 106.07,105.38 105.49,105.97 v3(103.38,105.97)
  BOTTOM w0.127: R246.1 91.27,137.83 91.27,137.23 91.68,136.82 91.68,135.47 91.06,134.84 91.06,115.7 101.42,105.33 102.74,105.33 v3(103.38,105.97)
D31: length 114.4
  TOP w0.102: 97.73,78.74 95,78.74 93.85,79.88 93.85,80.75 U13.E2
  TOP w0.127: 97.73,78.74 98.42,78.74 100.21,80.53 v1(100.21,80.76) ; CN11.21 v3(101.98,104.7)
  L4_SIG w0.102: v1(100.21,80.76) 100.2,80.76 99.8,81.17 99.8,86.06 99.9,86.16 100.21,86.16 100.31,86.06 100.31,84.58 100.41,84.48 100.62,84.48 100.72,84.58 100.72,86.06 100.82,86.16 101.02,86.16 101.13,86.06 101.13,84.58 101.23,84.48 101.43,84.48 101.53,84.58 101.53,86.06 101.63,86.16 101.84,86.16 101.94,86.06 101.94,84.58 102.04,84.48 102.24,84.48 102.34,84.58 102.34,86.06 102.45,86.16 102.65,86.16 102.75,86.06 102.75,84.58 102.85,84.48 103.06,84.48 103.16,84.58 103.16,86.06 103.26,86.16 103.46,86.16 103.56,86.06 103.56,84.58 103.67,84.48 103.87,84.48 103.97,84.58 103.97,86.06 104.07,86.16 104.28,86.16 104.38,86.06 104.38,84.58 104.48,84.48 104.68,84.48 104.78,84.58 104.78,86.06 104.88,86.16 105.11,86.16 105.23,86.03 105.23,84.61 105.36,84.48 105.61,84.48 105.74,84.61 105.74,102.67 105.64,102.77 104.29,102.77 104.19,102.87 104.19,103.07 104.29,103.18 105.64,103.18 105.74,103.28 105.74,103.48 105.64,103.58 104.29,103.58 104.19,103.68 104.19,103.89 104.29,103.99 105.64,103.99 105.74,104.09 105.74,104.29 105.64,104.4 104.29,104.4 104.19,104.5 104.19,104.7 104.29,104.8 105.64,104.8 105.74,104.9 105.74,105.11 105.56,105.28 102.04,105.28 101.98,105.22 v3(101.98,104.7)
  BOTTOM w0.127: R248.1 91.3,136.66 91.3,135.62 90.68,135 90.68,115.32 101.35,104.65 101.93,104.65 v3(101.98,104.7)
E5V: length 46.2
  TOP w0.508: L3.3 4.1,56.4 ; L3.3 2.91,55.21 ; L3.3 5.3,55.21 ; 4.57,64.19 4.57,65.15 ; 4.57,65.15 3.61,65.15 ; 4.57,65.15 4.57,66.12 ; 4.57,65.15 5.54,65.15 ; 15.16,54.74 C58.1 ; C58.1 17.91,56.46 ; C58.1 17.91,53.01 ; C58.1 20.65,54.74 ; v1(24.79,73.36) 24.79,75.97 25.78,76.96 D11.1
  BOTTOM w0.508: v1(24.79,73.36) 23.72,72.29 23.72,70.33 21.97,68.58 10.16,68.58 8,66.42 5.84,66.42 4.57,65.15
I2C1_SCL_C: length 5.9
  TOP w0.127: v1(150.69,150.69) CN4.13
  BOTTOM w0.127: T4.2 149.73,153.14 R183.2 150.37,151.51 150.37,151.02 v1(150.69,150.69) 151.44,150.69 R230.1
I2C1_SDA_C: length 5.6
  TOP w0.127: v1(153.8,150.69) CN4.14
  BOTTOM w0.127: T5.2 154.05,153.65 R298.2 154.05,150.95 v1(153.8,150.69) 153.73,150.62 R234.1
LCD_B0: length 171.1
  TOP w0.127: U4.B10 83.63,135.27 84.43,135.27 84.51,135.36 85.44,135.36 85.88,134.91 v5(85.89,134.91) ; v1(80.64,33.37) 80.71,33.37 80.96,33.12 CN20.21 ; CN6.27 111.1,139.45 111.86,140.21 112.14,140.21 v1(112.65,140.72)
  L4_SIG w0.102: v5(85.89,134.91) 85.89,134.45 86.61,133.73 86.92,133.73 86.92,133.73 89.41,133.73 90.93,135.25 95.12,135.25 99.19,139.32 108.58,139.32 109.98,140.72 v1(112.65,140.72)
  BOTTOM w0.127: v1(112.65,140.72) 113.13,140.24 117.48,140.24 120.93,136.79 120.93,127.91 121.64,127.2 121.64,123.09 120.7,122.15 120.7,118.77 115.01,113.08 115.01,91.82 114.63,91.44 114.63,78.72 78.87,42.96 78.87,35.05 80.55,33.37 v1(80.64,33.37)
LCD_B1: length 170.2
  TOP w0.127: U4.B9 83.22,136.49 83.62,136.09 86.41,136.09 86.68,135.82 86.68,135.5 86.89,135.28 v5(87.22,135.28) ; CN20.23 79.69,33.46 80.64,34.42 v1(80.64,34.54) ; CN6.26 v1(113.54,140.72)
  L4_SIG w0.102: v1(113.54,140.72) 112.9,141.35 110.11,141.35 108.46,139.7 98.93,139.7 94.91,135.68 90.72,135.68 89.66,134.62 87.88,134.62 v5(87.22,135.28)
  BOTTOM w0.127: v1(113.54,140.72) 117.64,140.72 121.21,137.14 121.21,128.02 121.89,127.33 121.89,122.86 121.06,122.02 121.06,118.49 115.32,112.75 115.32,91.54 114.94,91.16 114.94,78.37 79.25,42.68 79.25,36.07 80.64,34.67 v1(80.64,34.54)
LCD_B2: length 174.4
  TOP w0.127: U4.C9 v5(82.81,136.09) ; CN6.20 v1(113.54,144.53) ; CN20.25 78.42,35.37 v1(79.88,36.83)
  L4_SIG w0.102: v1(113.54,144.53) 113.03,145.03 111.12,145.03 107.31,141.22 97.16,141.22 92.96,137.03 85.7,137.03 84.75,136.09 v5(82.81,136.09)
  BOTTOM w0.127: v1(79.88,36.83) 80.39,37.34 80.39,38.23 80.01,38.61 80.01,42.15 115.49,77.63 115.49,90.7 115.87,91.08 115.87,112.29 121.79,118.21 121.79,121.64 123.14,122.99 123.14,137.01 115.62,144.53 v1(113.54,144.53)
LCD_B3: length 174.5
  TOP w0.127: CN20.27 77.15,35.12 v1(79.88,37.85) ; U4.D10 v5(82.01,135.29) ; CN6.22 v1(113.54,143.26)
  L4_SIG w0.102: v5(82.01,135.29) 82.45,135.73 84.93,135.73 85.98,136.78 93.22,136.78 95.54,139.1 95.54,139.27 95.82,139.55 95.99,139.55 97.28,140.84 107.82,140.84 110.87,143.89 112.9,143.89 v1(113.54,143.26)
  BOTTOM w0.127: v1(79.88,37.85) 79.63,38.1 79.63,42.34 115.21,77.93 115.21,90.96 115.6,91.34 115.6,112.52 121.41,118.34 121.41,121.74 122.86,123.19 122.86,127.3 121.82,128.35 121.82,137.74 116.3,143.26 v1(113.54,143.26)
LCD_B4: length 180.6
  TOP w0.127: CN20.29 75.88,35.37 79.63,39.12 v1(80.52,39.12) ; U4.D8 v5(82.01,136.89) ; CN6.16 v1(113.54,147.07)
  L4_SIG w0.102: v1(113.54,147.07) 112.9,147.7 111,147.7 108.46,145.16 95.89,145.16 92.2,141.48 90.3,141.48 89.28,140.46 87.38,140.46 86.74,139.83 86.26,139.83 84.96,138.53 84.96,137.03 84.73,136.8 83.62,136.8 83.13,137.29 82.41,137.29 v5(82.01,136.89)
  BOTTOM w0.127: v1(113.54,147.07) 114.35,147.07 116.42,144.99 116.42,144.4 123.39,137.42 123.39,118.8 116.51,111.91 116.51,77.87 80.52,41.88 v1(80.52,39.12)
LCD_B5: length 185.6
  TOP w0.127: v1(111.86,149.61) 111.86,149.15 111.05,148.34 CN6.13 ; CN20.31 74.61,35.37 79.57,40.33 v1(81.18,40.33) ; U4.D7 v5(81.21,138.49)
  L4_SIG w0.102: v5(81.21,138.49) 81.65,138.93 83.18,138.93 85.47,141.22 86.11,141.22 86.74,141.86 88.14,141.86 91.57,145.29 92.71,145.29 95.38,147.96 109.09,147.96 110.74,149.61 v1(111.86,149.61)
  BOTTOM w0.127: v1(111.86,149.61) 112.78,149.61 113.41,148.97 113.91,148.97 117.47,145.4 117.47,144.46 124,137.93 124,118.39 117.09,111.48 117.09,75.18 115.08,73.16 112.51,73.16 81.18,41.83 v1(81.18,40.33)
LCD_B6: length 185.3
  TOP w0.127: U4.C6 v5(82.81,139.29) ; CN20.33 73.34,34.99 79.25,40.89 v1(81.92,40.89) ; CN6.12 v1(113.54,149.61)
  L4_SIG w0.102: v5(82.81,139.29) 85.13,141.6 85.98,141.6 86.87,142.49 87.5,142.49 91.95,146.94 93.73,146.94 95.25,148.46 108.71,148.46 110.36,150.11 112.78,150.11 113.28,149.61 v1(113.54,149.61)
  BOTTOM w0.127: v1(113.54,149.61) 113.96,149.61 117.86,145.71 117.86,144.65 124.33,138.18 124.33,118.14 117.42,111.23 117.42,74.86 115.12,72.56 112.52,72.56 81.79,41.81 81.79,41.02 v1(81.92,40.89)
LCD_B7: length 187.6
  TOP w0.127: v1(82.3,41.53) 78.61,41.53 72.07,34.99 CN20.35 ; v1(111.94,150.55) 111.86,150.47 111.86,150.37 111.1,149.61 CN6.11 ; U4.C5 v5(82.81,140.09)
  L4_SIG w0.102: v1(111.94,150.55) 110.16,150.55 108.48,148.87 95.02,148.87 93.47,147.32 91.69,147.32 88.01,143.64 86.11,143.64 82.81,140.34 v5(82.81,140.09)
  BOTTOM w0.127: v1(111.94,150.55) 112.73,150.55 113.21,150.06 114.22,150.06 118.3,145.99 118.3,144.85 124.64,138.51 124.64,118.01 117.81,111.18 117.81,74.51 115.37,72.07 112.84,72.07 v1(82.3,41.53)
LCD_G0: length 180.3
  TOP w0.127: U4.J12 v5(77.21,133.69) ; CN5.53 v1(43.36,122.94) ; CN20.4 v1(92.39,25.15)
  L4_SIG w0.102: v5(77.21,133.69) 77.21,133.61 77.6,133.22 77.6,127.64 75.62,125.65 75.62,123.88 74.17,122.43 63.75,122.43 62.1,124.08 50.06,124.08 49.43,123.44 43.87,123.44 v1(43.36,122.94)
  BOTTOM w0.127: v1(43.36,122.94) 43.18,122.94 41.55,121.31 41.55,117.11 47.96,110.71 47.96,91.72 57.17,82.5 57.17,71.89 65.86,63.2 65.86,54.81 72.39,48.29 72.39,45.72 72.77,45.34 72.77,27.56 76.58,23.75 89.41,23.75 89.98,24.32 91.5,24.32 92.33,25.15 v1(92.39,25.15)
LCD_G1: length 176.8
  TOP w0.127: U4.H12 v5(78.01,133.69) ; v1(43.3,121.09) 42.61,120.4 CN5.57 ; v1(90.93,25.02) 91.12,25.21 CN20.6
  L4_SIG w0.102: v1(43.3,121.09) 44.46,122.25 45.64,122.25 46.2,122.81 49.89,122.81 50.39,123.32 61.72,123.32 63.25,121.79 75.06,121.79 76.96,123.7 76.96,125.73 78.49,127.25 78.49,133.17 78.01,133.65 v5(78.01,133.69)
  BOTTOM w0.127: v1(90.93,25.02) 87.12,25.02 86.74,24.64 76.71,24.64 74.68,26.67 74.68,29.35 73.91,30.11 73.91,48.95 67.41,55.45 67.41,64.11 58.31,73.21 58.31,83.26 49.1,92.48 49.1,111.18 42.93,117.35 42.93,120.71 43.3,121.08 v1(43.3,121.09)
LCD_G2: length 184.1
  TOP w0.127: CN20.8 89.85,24.57 90.68,23.75 v1(90.93,23.75) ; U4.J13 v5(77.21,132.89) ; CN5.45 v1(43.41,128.02)
  L4_SIG w0.102: v1(43.41,128.02) 44.04,127.38 44.91,127.38 46.18,126.11 62.1,126.11 64.26,123.95 73.03,123.95 73.28,124.21 73.28,126.75 77.21,130.68 v5(77.21,132.89)
  BOTTOM w0.127: v1(43.41,128.02) 43.31,128.02 40.67,125.37 40.67,116.79 47.19,110.26 47.19,91.34 56.41,82.12 56.41,71.1 65.02,62.48 65.02,54.25 70.41,48.87 70.41,46.94 72.39,44.96 72.39,27.18 76.33,23.24 90.42,23.24 v1(90.93,23.75)
LCD_G3: length 174.5
  TOP w0.127: v1(43.31,121.79) 43.18,121.67 CN5.55 ; U4.H13 v5(78.01,132.89) ; v1(88.58,24.38) CN20.10
  L4_SIG w0.102: v1(43.31,121.79) 44.02,122.5 45.31,122.5 45.92,123.11 49.66,123.11 50.24,123.7 61.98,123.7 63.5,122.17 74.55,122.17 75.95,123.57 75.95,125.35 78.01,127.41 v5(78.01,132.89)
  BOTTOM w0.127: v1(43.31,121.79) 43.18,121.79 42.32,120.93 42.32,117.42 48.72,111.02 48.72,92.23 57.93,83.01 57.93,72.77 66.91,63.79 66.91,55.21 73.53,48.59 73.53,29.97 74.17,29.34 74.17,26.67 76.71,24.13 88.33,24.13 v1(88.58,24.38)
LCD_G4: length 178.5
  TOP w0.127: v1(111.89,134.49) 111.76,134.37 CN6.35 ; CN20.12 v1(87.31,29.21) ; U4.G12 v5(79.61,133.69)
  L4_SIG w0.102: v1(111.89,134.49) 98.07,134.49 94.26,130.68 87.76,130.68 86.79,131.65 81.08,131.65 80.77,131.95 80.77,133.08 80.52,133.33 79.97,133.33 v5(79.61,133.69)
  BOTTOM w0.127: v1(87.31,29.21) 86.8,29.72 85.98,29.72 84.96,28.7 84.33,28.7 84.07,28.96 84.07,30.23 82.68,31.62 80.67,31.62 77.85,34.44 77.85,43.32 114.05,79.52 114.05,91.8 114.43,92.18 114.43,113.77 119.74,119.08 119.74,122.3 119.35,122.68 119.35,127.2 119,127.56 119,133.91 117.78,135.13 112.75,135.13 112.12,134.49 v1(111.89,134.49)
LCD_G5: length 179.1
  TOP w0.127: CN20.14 v1(86.04,29.08) ; CN6.37 111.73,133.1 v1(111.89,133.25) ; U4.G13 v5(79.61,132.89)
  L4_SIG w0.102: v5(79.61,132.89) 79.61,132 83.31,128.3 86.77,128.3 88.09,129.62 94.34,129.62 98.32,133.6 111.53,133.6 v1(111.89,133.25)
  BOTTOM w0.127: v1(111.89,133.25) 111.89,133.73 112.97,134.81 117.59,134.81 118.62,133.78 118.62,127.56 119.05,127.13 119.05,122.56 119.43,122.17 119.43,119.35 114.1,114.02 114.1,92.33 113.77,92 113.77,79.84 77.47,43.54 77.47,34.11 80.47,31.11 82.42,31.11 83.57,29.97 83.57,28.7 84.01,28.26 85.41,28.26 86.04,28.89 v1(86.04,29.08)
LCD_G6: length 172.9
  TOP w0.127: CN20.16 v1(84.77,29.34) ; CN6.34 v1(113.54,135.64) ; U4.F12 v5(80.41,133.69)
  L4_SIG w0.102: v5(80.41,133.69) 80.83,134.11 83.82,134.11 85.32,132.61 94.51,132.61 97.64,135.74 111.23,135.74 111.56,136.07 113.11,136.07 v1(113.54,135.64)
  BOTTOM w0.127: v1(84.77,29.34) 84.77,30.54 83.19,32.13 80.87,32.13 78.36,34.65 78.36,43.11 114.3,79.05 114.3,91.62 114.73,92.05 114.73,113.56 120.07,118.9 120.07,122.43 119.68,122.81 119.68,127.28 119.38,127.58 119.38,134.04 117.78,135.64 v1(113.54,135.64)
LCD_G7: length 173.1
  TOP w0.127: v1(112.9,133.73) 113.54,133.73 114.17,133.1 CN6.38 ; U4.F13 v5(80.41,132.89) ; CN20.18 83.5,28.51 v1(82.93,29.08)
  L4_SIG w0.102: v5(80.41,132.89) 80.41,131.81 81.03,131.19 86.74,131.19 87.76,130.18 94.39,130.18 98.22,134.01 112.62,134.01 v1(112.9,133.73)
  BOTTOM w0.127: v1(112.9,133.73) 113.16,133.73 113.79,134.37 117.35,134.37 118.24,133.48 118.24,127.56 118.75,127.05 118.75,122.38 119.08,122.05 119.08,119.51 113.79,114.22 113.79,92.46 113.41,92.08 113.41,80.16 76.96,43.71 76.96,33.88 80.24,30.61 82.04,30.61 82.93,29.72 v1(82.93,29.08)
LCD_R0: length 188.1
  TOP w0.127: v1(90.93,41.78) 92.39,40.32 CN20.3 ; U4.G4 v5(79.61,140.89) ; CN6.5 111.12,153.42 111.53,153.01 112.06,153.01 112.14,152.93 v1(112.24,152.93)
  L4_SIG w0.102: v1(112.24,152.93) 110.46,152.93 110.16,153.24 92.28,153.24 87.96,148.92 85.49,148.92 84.88,148.31 84.87,148.31 80.85,144.29 80.85,141.62 80.56,141.33 80.24,141.33 79.8,140.89 v5(79.61,140.89)
  BOTTOM w0.127: v1(112.24,152.93) 112.78,153.47 113.97,153.47 114.81,152.64 114.81,152.15 125.88,141.08 125.88,116.97 120.78,111.86 120.78,97.21 119.76,96.19 119.76,73.72 115.77,69.72 113.28,69.72 90.93,47.37 v1(90.93,41.78)
LCD_R1: length 158.2
  TOP w0.127: v1(44.96,122.94) CN5.54 49.32,122.94 64.18,137.79 68.58,137.79 70.08,139.29 72.4,139.29 U4.R6 ; CN20.5 91.12,39.18 82.42,47.88 71.58,47.88 v1(70.94,47.24)
  BOTTOM w0.127: v1(70.94,47.24) 70.94,48.95 65.48,54.41 65.48,62.89 56.79,71.58 56.79,82.38 47.57,91.59 47.57,110.47 41.17,116.88 41.17,121.44 43.31,123.57 44.32,123.57 v1(44.96,122.94)
LCD_R2: length 143.8
  TOP w0.102: 71.63,137.92 72.64,137.92 U4.R7
  TOP w0.127: CN5.58 v1(48.84,120.4) 62.94,134.49 66.67,134.49 70.1,137.92 71.63,137.92 ; v1(74.93,46.86) 82.3,46.86 89.85,39.31 CN20.7
  BOTTOM w0.127: v1(74.93,46.86) 74.93,49.78 68.63,56.08 68.63,64.97 59.97,73.63 59.97,84.55 50.62,93.9 50.62,111.94 48.84,113.72 v1(48.84,120.4)
LCD_R3: length 154.4
  TOP w0.127: U4.P7 73.24,138.46 72.66,138.46 72.3,138.81 70.36,138.81 66.55,135 62.61,135 49.28,121.67 CN5.56 45.03,121.67 v1(44.88,121.82) ; CN20.9 88.58,39.69 82.17,46.1 v1(73.03,46.1)
  BOTTOM w0.127: v1(73.03,46.1) 73.03,48.41 66.34,55.09 66.34,63.53 57.55,72.32 57.55,82.76 48.34,91.97 48.34,110.9 41.94,117.3 41.94,121.18 43.05,122.3 44.4,122.3 v1(44.88,121.82)
LCD_R4: length 175.8
  TOP w0.102: U4.N8 v5(74.81,136.89)
  TOP w0.127: v1(68.45,47.75) 70.73,45.48 82.03,45.48 87.31,40.2 CN20.11 ; v1(44.7,136.02) 43.43,136.02 42.55,136.91 CN5.31
  L4_SIG w0.102: v1(44.7,136.02) 44.83,136.14 54.03,136.14 56.62,133.55 66.55,133.55 68.78,135.79 73.18,135.79 73.66,136.27 74.19,136.27 v5(74.81,136.89)
  BOTTOM w0.127: v1(68.45,47.75) 68.38,47.75 63.04,53.09 63.04,61.29 54.89,69.45 54.89,81.25 45.67,90.46 45.67,109.27 38.99,115.95 38.99,125.86 37.97,126.87 37.97,131.19 39.58,132.79 45.31,132.79 45.87,133.35 45.87,134.85 v1(44.7,136.02)
LCD_R5: length 170.5
  TOP w0.127: U4.M9 v5(74.81,136.09) ; CN5.34 v1(48.77,135.64) ; CN20.13 86.04,40.58 81.63,44.99 69.18,44.99 v1(68.45,45.72)
  L4_SIG w0.102: v1(48.77,135.64) 53.9,135.64 56.49,133.05 66.6,133.05 68.81,135.25 73.41,135.25 74.04,135.89 74.55,135.89 74.75,136.09 v5(74.81,136.09)
  BOTTOM w0.127: v1(48.77,135.64) 48.77,135.23 45.92,132.38 40.57,132.38 39.59,131.41 38.95,131.41 38.35,130.81 38.35,127.13 39.38,126.1 39.38,116.22 46.05,109.55 46.05,90.58 55.27,81.36 55.27,69.8 63.54,61.53 63.54,53.38 68.9,48.01 68.9,46.17 v1(68.45,45.72)
LCD_R6: length 171
  TOP w0.127: CN20.15 84.77,41.08 81.53,44.32 v1(68.71,44.32) ; v1(44.83,130.23) 45.16,130.56 CN5.42 ; v5(74.41,130.36) 74.41,130.8 74.8,131.19 74.8,132.08 U4.M14
  L4_SIG w0.102: v1(44.83,130.23) 49.2,130.23 49.96,129.46 62.83,129.46 65.55,126.75 71.37,126.75 74.41,129.78 v5(74.41,130.36)
  BOTTOM w0.127: v1(68.71,44.32) 69.35,44.97 69.35,48.33 64.06,53.62 64.06,61.82 55.65,70.23 55.65,81.59 46.43,90.8 46.43,109.68 39.76,116.34 39.76,126.61 38.73,127.64 38.73,130.55 39.34,131.15 39.71,131.15 40.13,131.57 42.93,131.57 43.69,130.81 43.94,130.81 44.58,130.18 44.83,130.18 v1(44.83,130.23)
LCD_R7: length 165.9
  TOP w0.127: CN20.17 83.5,41.41 81.2,43.71 v1(69.8,43.71) ; CN5.44 v1(44.83,129.29) ; U4.K12 v5(76.41,133.69)
  L4_SIG w0.102: v5(76.41,133.69) 76.41,133.65 76.83,133.22 76.83,132.21 75.95,131.32 75.95,130.43 71.37,125.86 65.18,125.86 63.78,127.25 50.95,127.25 48.92,129.29 v1(44.83,129.29)
  BOTTOM w0.127: v1(69.8,43.71) 69.8,48.64 64.54,53.9 64.54,62.2 56.03,70.72 56.03,81.87 46.81,91.08 46.81,110.01 40.26,116.56 40.26,125.73 43.31,128.78 44.32,128.78 v1(44.83,129.29)
LED_STLINK: length 35.9
  TOP w0.127: v1(36.2,36.45) 35.94,36.71 U21.30 ; R201.1 R202.1 v1(16.26,16.51)
  BOTTOM w0.127: v1(36.2,36.45) 36.2,35.43 32.77,32 32.77,30.28 26.49,24 26.49,20.78 22.23,16.51 v1(16.26,16.51)
LOOP: length 11.1
  TOP w0.127: TP15.1 62.23,24.64 60.45,26.42 60.45,30.86 59.91,31.41 U22.14
MFX_SWCLK: length 7.6
  TOP w0.127: U22.37 49.49,36.41 48.39,35.31 44.83,35.31 CN19.3
MFX_SWDIO: length 11.8
  TOP w0.127: CN19.1 44.83,40.39 52.2,40.39 52.73,39.85 U22.34
MIC_CLK: length 130.9
  BOTTOM w0.127: CN24.3 123.44,13.19 123.44,14.48 SB20.1 122.68,16.13 122.17,16.64 118.75,16.64 118.24,17.14 94.74,17.14 92.33,14.73 JP19.2 89.41,13.46 84.84,13.46 82.3,16 69.22,16 60.07,6.86 51.56,6.86 47.88,3.17 34.54,3.17 25.78,11.94 11.33,11.94 11.09,11.7 CN27.3
MIC_DATA: length 145.9
  BOTTOM w0.127: CN27.1 3.83,11.7 5.23,13.11 9.8,13.11 10.32,12.59 25.89,12.59 34.67,3.81 46.99,3.81 51.05,7.87 60.07,7.87 67.18,14.99 67.18,17.14 68.58,18.54 82.3,18.54 JP18.2 87.5,14.73 88.77,16 91.95,16 94.11,18.16 119.76,18.16 120.4,17.53 127.64,17.53 129.16,16 SB21.2 129.16,13.84 128.4,13.08 128.4,13.07 CN24.1
MIC_VDD: length 154.7
  TOP w0.127: U24.1 125.65,15.66 126.36,16.38 C89.1 127.64,18.43 CN24.4 126.03,17.59 123,17.59 R199.2 121.16,15.75 121.16,15.62 R198.2 v1(119.38,14.86) ; v1(9.78,9.4) 9.4,9.02 8,9.02 7.49,9.53 6.48,9.53 5.63,8.68 U25.1
  L4_SIG w0.102: v1(9.78,9.4) 5.97,9.4 3.81,7.24 CN27.4
  BOTTOM w0.127: v1(9.78,9.4) 9.91,9.53 14.73,9.53 16.51,11.3 25.53,11.3 34.44,2.39 48.67,2.39 52.35,6.07 60.3,6.07 68.96,14.73 JP17.2 83.69,12.57 83.69,11.18 84.33,10.54 91.44,10.54 92.08,11.18 92.08,12.57 95.76,16.26 116.46,16.26 117.73,14.99 119.25,14.99 v1(119.38,14.86)
